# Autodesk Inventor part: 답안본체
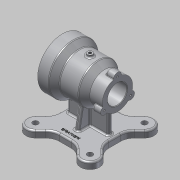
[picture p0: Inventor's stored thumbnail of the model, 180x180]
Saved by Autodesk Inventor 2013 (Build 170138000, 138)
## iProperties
Created: 2017-03
Part Number: 답안본체
Material: 알루미늄 6061
Document SubType Name: Modeling
Designer: Administrator
Density: 2.71 g/cm^3
Mass: 1007.36 g
Surface Area: 842.208 cm^2
Volume: 371.721 cm^3
Author: Administrator
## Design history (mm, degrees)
sketch "스케치2"
  geometry: L1 (0, 0)-(-100, 0); L2 (-100, 18.5)-(-100, 27.5); L3 (-100, 27.5)-(-77, 27.5); L4 (-77, 27.5)-(-65, 36); L5 (-65, 36)-(-31, 36); L6 (-31, 36)-(-20, 45); L7 (-20, 45)-(0, 45); L8 (0, 45)-(0, 36); L9 (-1, 35)-(-20, 35); L10 (-23, 32)-(-23, 29); L11 (-26, 26)-(-67, 26); L12 (-70, 23)-(-70, 20.5); L13 (-73, 17.5)-(-99, 17.5); L14 (-1, 35)-(0, 36); L15 (-99, 17.5)-(-100, 18.5); A1 r 3 centre (-20, 32) between (-20, 35) and (-23, 32); A2 r 3 centre (-26, 29) between (-26, 26) and (-23, 29); A3 r 3 centre (-67, 23) between (-67, 26) and (-70, 23); A4 r 3 centre (-73, 20.5) between (-73, 17.5) and (-70, 20.5); 6 further points
  constraints: 30 end point, 14 point on line, 8 point on circle, 8 tangent, 5 parallel, 5 perpendicular, 4 centre point, 3 equal radius, 1 horizontal
  dimensions: "d0" = 100 distance of L1.start L1.end; "d2" = 90 diameter of L7 L1; "d3" = 20 distance of L6.end L7.end; "d4" = 31 horizontal distance of L5.end L7.end; "d5" = 65 horizontal distance of L4.end L7.end; "d6" = 23 distance of L2.end L3.end; "d7" = 72 diameter of L5 L1; "d8" = 55 diameter of L3 L1; "d9" = 70 diameter of L9 L1; "d10" = 52 diameter of L11 L1; "d11" = 35 diameter of L13 L1; "d12" = 23 distance between parallel lines of L10 L8; "d13" = 47 distance of point (-23, 26) point (-70, 26); "d14" = 3 radius of A1; "d15" = 1 distance of L9.start point (0, 35); "d16" = 1 distance of L8.end point (0, 35) (= d15); "d17" = 1 distance of L13.end point (-100, 17.5) (= d15); "d18" = 1 distance of L2.start point (-100, 17.5) (= d17)
revolve "회전1" sketch "스케치2" stored, may be unused: angle "d19" = 90 deg
node "작업 평면3"
sketch "스케치4"
  geometry: L1 (100, 27.5)-(100, -27.5) reference; L2 (0, 0)-(100, 0); L3 (50, 0)-(50, -68.709); L4 (39.397, 45)-(60.603, 45); L5 (95, 10.603)-(95, -10.603); L6 (60.603, -45)-(39.397, -45); L7 (5, -10.603)-(5, 45); L8 (5, 45)-(95, -45); L9 (95, 45)-(5, -45); L10 (50, 0)-(0.503, 49.497); L11 (50, 0)-(99.497, 49.497); L12 (50, 0)-(0.503, -49.497); L13 (50, 0)-(99.497, -49.497); L14 (12.523, 61.518)-(21.719, 52.322); L15 (-11.518, 37.477)-(5, 20.958); L16 (-11.518, -37.477)-(-2.322, -28.281); L17 (12.523, -61.518)-(21.719, -52.322); L18 (87.477, -61.518)-(78.281, -52.322); L19 (111.518, -37.477)-(102.322, -28.281); L20 (87.477, 61.518)-(78.281, 52.322); L21 (111.518, 37.477)-(102.322, 28.281); A1 r 70 centre (50, 0) between (0.503, 49.497) and (99.497, 49.497); A2 r 17 centre (0.503, 49.497) between (12.523, 61.518) and (-11.518, 37.477); A3 r 17 centre (99.497, -49.497) between (87.477, -61.518) and (111.518, -37.477); A4 r 17 centre (0.503, -49.497) between (-11.518, -37.477) and (12.523, -61.518); A5 r 17 centre (99.497, 49.497) between (87.477, 61.518) and (111.518, 37.477); A6 r 25 centre (39.397, 70) between (21.719, 52.322) and (39.397, 45); A7 r 25 centre (60.603, 70) between (60.603, 45) and (78.281, 52.322); A8 r 25 centre (120, 10.603) between (102.322, 28.281) and (95, 10.603); A9 r 25 centre (120, -10.603) between (95, -10.603) and (102.322, -28.281); A10 r 25 centre (39.397, -70) between (39.397, -45) and (21.719, -52.322); A11 r 25 centre (-20, -10.603) between (-2.322, -28.281) and (5, -10.603); A12 r 25 centre (60.603, -70) between (78.281, -52.322) and (60.603, -45); 1 further point
  constraints: 40 end point, 26 point on circle, 22 tangent, 12 centre point, 12 point on line, 8 equal radius, 7 parallel, 6 midpoint, 5 coincident, 5 perpendicular, 1 collinear, 1 horizontal
  dimensions: "d38" = 140 diameter of A1; "d40" = 90 distance of L7.end L9.start; "d41" = 90 distance of L9.start L8.end; "d42" = 45 deg angle of L2 L10; "d43" = 90 deg angle of L11 L8; "d44" = 90 deg angle of L12 L13; "d45" = 34 diameter of A2; "d46" = 25 radius of A6; "d95" = 25 radius of A12
extrude "돌출2" join sketch "스케치4" distance "d47" = 12; taper "d48" = 0 deg
sketch "스케치5"
  geometry: L1 (39.397, -45)-(60.603, -45) reference; L2 (60.603, 45)-(39.397, 45) reference; L3 (50, 45)-(50, -45); L4 (50, 0)-(13, 0); L5 (13, 0)-(50, 0); L6 (87, 0)-(50, 0); L7 (87, 0)-(87, 4); L8 (87, 4)-(13, 4); L9 (13, 4)-(13, -4); L10 (13, -4)-(87, -4); L11 (87, -4)-(87, 0); 2 further points
  constraints: 18 end point, 4 collinear, 4 perpendicular, 3 midpoint, 2 parallel
  dimensions: "d52" = 4 distance between parallel lines of L8 L4; "d53" = 8 distance of L8.end L9.end; "d54" = 37 horizontal distance of L4.start L9.end; "d55" = 37 distance of L6.start L4.start
extrude "돌출3" join sketch "스케치5" stored distance "d56" = 12; taper "d57" = 0 deg
node "작업 평면4"
sketch "스케치6"
  geometry: L1 (-28.281, -70)-(-10.603, -70) reference; L2 (-28.281, -70)-(-37.477, -70) reference; L3 (-37.477, -70)-(-66.497, -70) reference; L4 (37.477, -70)-(20.958, -70) reference; L5 (66.497, -70)-(37.477, -70) reference; L6 (18.14, -31.096)-(25, -70); A1 r 36 centre (0, 0) between (4, -35.777) and (-4, -35.777) reference; 3 further points
  constraints: 2 end point, 1 point on circle, 1 point on line
  dimensions: "d62" = 100 deg angle of L5 L6; "d63" = 25 horizontal distance of L6.end point (0, 0)
feature "리브1" sketch "스케치6" dims "d64" = 1, "d65" = 8, "d66" = 0, "d67" = 0, "d68" = 1, "d69" = 1
sketch "스케치7"
  geometry: L1 (-28.281, -70)-(-10.603, -70) reference; L2 (-37.477, -70)-(-66.497, -70) reference; L3 (-28.281, -70)-(-37.477, -70) reference; L4 (-18.14, -31.096)-(-25, -70); A1 r 36 centre (0, 0) between (4, -35.777) and (-4, -35.777) reference; 2 further points
  constraints: 2 end point, 1 point on circle, 1 point on line
  dimensions: "d70" = 25 horizontal distance of point (0, 0) L4.end; "d71" = 100 deg angle of L2 L4
feature "리브2" sketch "스케치7" dims "d72" = 1, "d73" = 8, "d74" = 0, "d75" = 0, "d76" = 1, "d77" = 1
sketch "스케치8"
  geometry: L1 (-27.5, 0)-(0, 0); L2 (0, 0)-(13.75, -23.816); L3 (0, 0)-(13.75, 23.816); C1 r 20.5 at (0, 0) reference; C2 r 7 at (-27.5, 0); C3 r 26 at (0, 0) reference; A1 r 27.5 centre (0, 0) between (-27.5, 0) and (13.75, -23.816) reference
  constraints: 6 end point, 3 point on circle, 1 centre point, 1 horizontal, 1 horizontal alignment
  dimensions: "d78" = 14 diameter of C2; "d81" = 120 deg angle of L1 L2; "d83" = 120 deg angle of L1 L3
extrude "돌출4" join sketch "스케치8" distance "d85" = 15; taper "d86" = 0 deg
fillet "모깎기1" dims "d90" = 1
fillet "모깎기2" dims "d91" = 3
fillet "모깎기3" dims "d92" = 1
fillet "모깎기4" dims "d93" = 3
fillet "모깎기5" dims "d94" = 3
fillet "모깎기6" dims "d96" = 3
sketch "스케치9"
  geometry: L1 (-5, 35.651)-(-5, 40); L2 (-5, 40)-(5, 40); L3 (5, 35.651)-(5, 40); A1 r 36 centre (0, 0) between (4, -35.777) and (-4, -35.777) reference; A2 r 36 centre (0, 0) between (-4, -35.777) and (4, -35.777) reference; 1 further point
  constraints: 6 end point, 4 point on circle, 2 perpendicular, 1 parallel, 1 vertical
  dimensions: "d98" = 40 distance from line of L2 point (0, 0); "d99" = 10 distance of L1.end L2.end
extrude "돌출5" join sketch "스케치9" stored distance "d100" = 10; taper "d101" = 0 deg
fillet "모깎기8" dims "d102" = 5
fillet "모깎기9" dims "d103" = 3
sketch "스케치10"
  geometry: C1 r 5 at (0.503, 49.497); C2 r 5 at (99.497, 49.497); C3 r 5 at (99.497, -49.497); C4 r 5 at (0.503, -49.497); A1 r 14 centre (0.503, -49.497) between (-9.397, -39.598) and (10.402, -59.397) reference; A2 r 14 centre (99.497, -49.497) between (89.598, -59.397) and (109.397, -39.598) reference; A3 r 14 centre (99.497, 49.497) between (109.397, 39.598) and (89.598, 59.397) reference; A4 r 14 centre (0.503, 49.497) between (10.402, 59.397) and (-9.397, 39.598) reference; 1 further point
  constraints: 4 centre point, 4 coincident, 3 equal radius
  dimensions: "d104" = 10 diameter of C1
extrude "돌출6" cut sketch "스케치10" stored distance "d106" = 10; taper "d107" = 0 deg
fillet "모깎기11" dims "d109" = 3
sketch "스케치11"
  geometry: C1 r 5 at (0, 0) reference; C2 r 2.5 at (0, 0); 1 further point
  constraints: 1 centre point, 1 coincident
  dimensions: "d110" = 5 diameter of C2
extrude "돌출7" cut sketch "스케치11" stored distance "d112" = 10; taper "d113" = 0 deg
feature "스레드1" dims "d114" = 10, "d115" = 0
sketch "스케치12"
  geometry: C1 r 2 at (0, 0); A1 r 7 centre (0, 0) between (0.127, 6.999) and (0.127, -6.999) reference
  constraints: 1 centre point, 1 coincident
  dimensions: "d116" = 4 diameter of C1
hole "구멍1" sketch "스케치12" at (0, 0) diameter "d118" = 3.242; stored, may be unused: countersink angle "d122" = 90 deg, drill point angle "d124" = 118 deg; dims "d119" = 9, "d120" = 4, "d121" = 2, "d123" = 11
sketch "스케치13" dims "d128" = 80
  geometry: C1 r 36 at (0, 0) reference; C2 r 45 at (0, 0) reference; C3 r 2 at (40, 0); 1 further point
  constraints: 2 horizontal alignment, 1 centre point, 1 coincident, 2 other
  dimensions: "d131" = 4 diameter of C3
hole "구멍2" sketch "스케치13" at (40, 0) diameter "d132" = 3.242; stored, may be unused: countersink angle "d136" = 90 deg, drill point angle "d138" = 118 deg; dims "d133" = 9, "d134" = 4, "d135" = 2, "d137" = 11
sketch "스케치14"
  geometry: L1 (17.643, -32.598)-(82.357, -32.598); L2 (82.357, -32.598)-(82.357, -37.402); L3 (82.357, -37.402)-(17.643, -37.402); L4 (17.643, -37.402)-(17.643, -32.598); L5 (17.643, -35)-(82.357, -35); L6 (50, -32.598)-(50, -37.402); L7 (95, -10.603)-(95, 10.603) reference; 1 further point
  constraints: 4 end point, 4 midpoint, 2 other
  dimensions: "d142" = 35 distance from line of L5 point (0, 0); "d143" = 45 distance between parallel lines of L6 L7
extrude "돌출8" join sketch "스케치14" distance "d144" = 0.5; taper "d145" = 0 deg
chamfer "모따기1" distance "d147" = 1; stored, may be unused: second distance "d148" = 2, angle "d149" = 45 deg
node "솔리드1"
pattern_circular "원형 패턴1" dims angle "d88" = 360 deg
pattern_circular "원형 패턴2" dims angle "d126" = 360 deg
pattern_circular "원형 패턴3" dims angle "d140" = 360 deg
other parameters: "d35" = -82
